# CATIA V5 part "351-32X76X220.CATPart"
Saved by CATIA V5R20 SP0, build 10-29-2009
Part number: 351-32X76X220
Definition: NONE
Nomenclature: 351-32X76X220
Source: Unknown
Description: 351-32X76X220
Bounding box of the stored display mesh (mm): x -7 to 213, y -22.5 to 22.5, z -22.5 to 22.5
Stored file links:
  C:\Users\Utente\Desktop\IO LAVORO\3D X SITO CF\X SITO\PLASTICA\351\351-32X76X220.CATPart
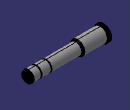
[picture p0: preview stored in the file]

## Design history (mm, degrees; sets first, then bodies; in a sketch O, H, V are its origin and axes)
Body1 "351-32X76X220" (main body)
  Solid1: solid without history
